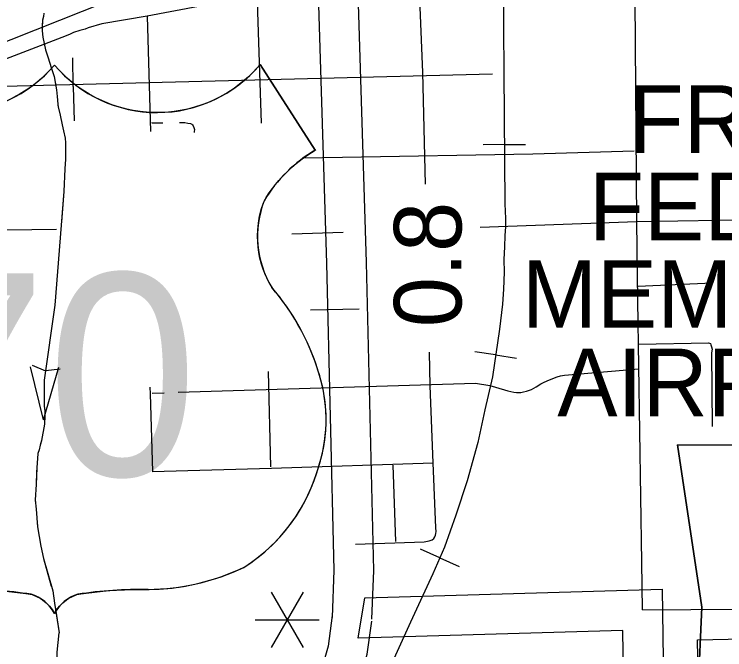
# Model space of a CAD drawing. Extents: x 1084508 to 1142749, y 1057638 to 1093403.
# Drawn here: x 1101630 to 1103026, y 1073047 to 1074295 of the extents above; entities that cross this region are included whole.
import ezdxf

# ---------------------------------------------------------------- set-up
doc = ezdxf.new("R2010")
doc.units = 0
for name, color, linetype in [('Level 10', 7, 'Continuous'), ('Level 15', 7, 'Continuous'), ('Level 21', 7, 'Continuous'), ('Level 22', 7, 'Continuous'), ('Level 33', 7, 'Continuous'), ('Level 34', 7, 'Continuous'), ('Level 35', 7, 'Continuous'), ('Level 40', 7, 'Continuous'), ('Level 43', 7, 'Continuous'), ('Level 48', 7, 'Continuous'), ('Level 57', 7, 'Continuous'), ('Level 6', 7, 'Continuous')]:
    doc.layers.add(name, color=color, linetype=linetype)

msp = doc.modelspace()

# ---------------------------------------------------------------- linework, layer by layer
at = {"layer": 'Level 10'}
msp.add_line((1102305.5, 1073070), (1102319.1, 1073148.9), dxfattribs=at)
for points in [[(1102319.1, 1073148.9), (1102903.4, 1073165.9), (1102916.4, 1072247.3), (1102924.5, 1071432.2), (1102929.4, 1071239.5), (1102926.3, 1071187.3), (1102905.3, 1071089.9)], [(1102848.9, 1071200.7), (1102848.3, 1071197.9), (1102850.9, 1071240.8), (1102846.1, 1071430.8), (1102838, 1072246.4), (1102826.1, 1073085.2), (1102305.5, 1073070)]]:
    msp.add_lwpolyline(points, dxfattribs=at)
at = {"layer": 'Level 15'}
for points in [[(1102224.1, 1074440.9), (1102243.7, 1073805.7), (1102258.1, 1073203.6), (1102254.5, 1073110.5)], [(1102332.9, 1073107.4), (1102336.7, 1073203), (1102322.2, 1073807.9), (1102302.5, 1074443.4)], [(1102254.8, 1073114.2), (1102246.6, 1073054.1), (1102235.2, 1073013), (1102230.6, 1072998.9), (1102210.8, 1072969.7), (1102197.7, 1072955.1), (1102173.8, 1072922.9), (1102155, 1072900), (1102143.6, 1072888.3), (1102116.9, 1072867), (1101851.5, 1072624), (1101364.1, 1072185.3), (1100217.6, 1071166.4), (1099385.1, 1070422.3)], [(1099437.4, 1070363.8), (1100269.9, 1071107.8), (1101416.4, 1072126.8), (1101904.3, 1072565.9), (1102168, 1072807.4), (1102196.3, 1072830.1), (1102213.4, 1072847.6), (1102235.6, 1072874.5), (1102258.6, 1072905.4), (1102272.7, 1072921.2), (1102301.9, 1072964.1), (1102310.4, 1072990.5), (1102323.6, 1073038.2), (1102332.6, 1073103.6)]]:
    msp.add_lwpolyline(points, dxfattribs=at)
at = {"layer": 'Level 21'}
for p, q in [((1102980.8, 1073131.1), (1102933.1, 1073449.7)), ((1102959.6, 1072647.8), (1102980.8, 1073131.1))]:
    msp.add_line(p, q, dxfattribs=at)
msp.add_lwpolyline([(1102933.1, 1073449.7), (1102980.8, 1073131.1), (1102959.6, 1072647.8), (1103002.1, 1072621.3), (1103081.7, 1072621.3), (1103081.7, 1072451.4), (1103750.8, 1072451.4), (1103782.7, 1072520.4), (1103772.1, 1072631.9), (1103788, 1072759.4), (1103846.4, 1072860.3), (1103883.6, 1072934.6), (1103936.7, 1073014.3), (1103968.6, 1073099.2), (1103995.1, 1073168.2), (1104042.9, 1073226.7), (1104053.5, 1073263.8), (1104032.3, 1073290.4), (1103867.7, 1073290.4), (1103904.8, 1073364.7), (1103910.1, 1073412.5), (1103888.1, 1073449.2)], close=True, dxfattribs=at)
msp.add_lwpolyline([(1102933.1, 1073449.7), (1103888.1, 1073449.2)], dxfattribs=at)
at = {"layer": 'Level 22'}
msp.add_line((1102113, 1074196.4), (1102221.6, 1074028.4), dxfattribs=at)
for points in [[(1101709.1, 1074195.5), (1101700.8, 1074186.2), (1101692.9, 1074178.1), (1101683.9, 1074169.7), (1101674.2, 1074161.4), (1101664.9, 1074154.2), (1101653.6, 1074146.2), (1101641.4, 1074138.6), (1101627.5, 1074131)], [(1102110.9, 1073230), (1102124, 1073241), (1102136.8, 1073252.8), (1102151.8, 1073268.4), (1102163.4, 1073281.9), (1102173.7, 1073295.1), (1102184.3, 1073310.3), (1102194.5, 1073326.8), (1102202.4, 1073341.1), (1102209.5, 1073355.8), (1102215.7, 1073370), (1102222.9, 1073389.4), (1102227.9, 1073405.4), (1102231.6, 1073418.2), (1102234.5, 1073429.5), (1102237.4, 1073442.5), (1102240.2, 1073459.5), (1102242, 1073477.6), (1102242.7, 1073492.9), (1102242.7, 1073508.6), (1102241.7, 1073525.3), (1102239.9, 1073540.6), (1102237.5, 1073555.3), (1102233.8, 1073571.8), (1102229.9, 1073586), (1102225.7, 1073599), (1102220.4, 1073614.7), (1102215.6, 1073627.5), (1102211.5, 1073637.4), (1102205.6, 1073650.9), (1102199.1, 1073664.5), (1102192.9, 1073676.3), (1102187.5, 1073686.2), (1102181.3, 1073696.7), (1102173.9, 1073708.4), (1102165.8, 1073720.4), (1102157.2, 1073732.4), (1102146.6, 1073746), (1102137.8, 1073756.5), (1102130.6, 1073768.2), (1102123.5, 1073783), (1102119, 1073794.4), (1102115.7, 1073804.7), (1102112.7, 1073816.3), (1102110.6, 1073827.1), (1102109.1, 1073838.5), (1102108.3, 1073847.9), (1102108, 1073859.5), (1102108.4, 1073872), (1102109.7, 1073884.8), (1102112.1, 1073898.7), (1102115.3, 1073911.7), (1102119.6, 1073924.8), (1102125.1, 1073935.4), (1102131.1, 1073944.5), (1102137.3, 1073953.2), (1102143.4, 1073961.1), (1102149.6, 1073968.5), (1102158.2, 1073978.1), (1102166.6, 1073986.6), (1102174.9, 1073994.4), (1102184.2, 1074002.4), (1102195.9, 1074011.5), (1102204.6, 1074017.7), (1102213.9, 1074023.7), (1102221.6, 1074028.4), (1102113, 1074196.4), (1102106.5, 1074189), (1102098.5, 1074180.5), (1102090.3, 1074172.6), (1102082.3, 1074165.5), (1102072.8, 1074157.8), (1102061.8, 1074149.7), (1102049.8, 1074141.8), (1102039, 1074135.5), (1102027.4, 1074129.4), (1102014.7, 1074123.5), (1102000.7, 1074118), (1101984.2, 1074112.6), (1101970.6, 1074109.1), (1101955.9, 1074106.1), (1101944.3, 1074104.4), (1101932.8, 1074103.1), (1101920.7, 1074102.4), (1101906.8, 1074102.2), (1101889.7, 1074103), (1101877.3, 1074104.3), (1101863.7, 1074106.4), (1101850.9, 1074109.1), (1101836.9, 1074112.7), (1101821.7, 1074117.6), (1101808.2, 1074122.9), (1101790.6, 1074131), (1101776.7, 1074138.6), (1101764.6, 1074146.2), (1101753.2, 1074154.2), (1101743.9, 1074161.4), (1101734.2, 1074169.7), (1101725.2, 1074178.1), (1101717.3, 1074186.2), (1101709.1, 1074195.5)], [(1101709.1, 1073118.3), (1101713.8, 1073126.1), (1101719.1, 1073132.9), (1101725.6, 1073139.5), (1101732.4, 1073144.9), (1101737.3, 1073148.2), (1101743, 1073151.3), (1101752.9, 1073155.4), (1101761.1, 1073157), (1101771, 1073158.4), (1101787.5, 1073160.5), (1101804.3, 1073162.2), (1101817.5, 1073163.3), (1101830.9, 1073164.2), (1101846.3, 1073165), (1101862.4, 1073165.5), (1101878.6, 1073165.7), (1101895.3, 1073165.6), (1101914.7, 1073166.3), (1101940.1, 1073168.4), (1101960.3, 1073171.2), (1101979, 1073174.7), (1101999, 1073179.3), (1102016.7, 1073184.2), (1102036.3, 1073190.6), (1102060.4, 1073199.8), (1102080.9, 1073209), (1102097.3, 1073219.7), (1102110.9, 1073230)], [(1101613.8, 1073162.2), (1101630.7, 1073160.5), (1101647.2, 1073158.4), (1101657.1, 1073157), (1101665.2, 1073155.4), (1101675.1, 1073151.3), (1101680.8, 1073148.2), (1101685.7, 1073144.9), (1101692.5, 1073139.5), (1101699, 1073132.9), (1101704.3, 1073126.1), (1101709.1, 1073118.3)]]:
    msp.add_lwpolyline(points, dxfattribs=at)
for centre, radius, start, end in [((1101507.5, 1074366.6), 264.4, 220.075, 319.6701), ((1101910.6, 1074366.6), 264.4, 220.3299, 319.925), ((1102363.6, 1073784.4), 282.3, 120.0117, 149.2191), ((1102301.5, 1073858.9), 193.5, 158.7892, 211.1895), ((1101795.5, 1073462.2), 451.5, 17.3087, 41.0435), ((1101944.5, 1073499.2), 298.3, 342.6181, 19.0424), ((1101895.9, 1073500.1), 345.2, 302.8688, 344.8926), ((1101889.5, 1073608.8), 443.2, 270.4221, 295.9229), ((1101538.9, 1072353.8), 811.9, 81.1942, 90.9539), ((1101879.3, 1072353.8), 811.9, 89.0461, 98.8058), ((1101640.4, 1073081.7), 77.8, 28.0342, 72.9864), ((1101777.7, 1073081.7), 77.8, 107.0136, 151.9658)]:
    msp.add_arc(centre, radius, start, end, dxfattribs=at)
at = {"layer": 'Level 33'}
for points in [[(1103154, 1074659), (1103175.5, 1073892.7), (1102853.2, 1073887.4), (1102545.7, 1073876.2)], [(1102863.3, 1073218.9), (1102855.6, 1073732.4), (1102853.2, 1073887.4), (1102849, 1074500.2)], [(1102105.3, 1074387.8), (1102107.1, 1074319.9), (1102115, 1074081.1)], [(1102227.8, 1074319.9), (1102106.5, 1074319), (1102070, 1074318.3), (1102057.4, 1074318.4), (1102049.3, 1074318), (1102035.5, 1074316.1), (1102024.2, 1074314.7), (1102010.2, 1074312.5), (1101999.9, 1074311.1), (1101992.3, 1074310.7), (1101890.9, 1074291.4), (1101802, 1074276.1), (1101774.9, 1074268.6), (1101769.1, 1074266.1), (1101758.8, 1074263.1), (1101746.7, 1074259.1), (1101739.6, 1074256.3), (1101731.9, 1074252.5), (1101259.9, 1074071.7), (1101243, 1074064), (1101239.3, 1074062.3), (1101235.3, 1074059), (1101228.7, 1074052.4), (1101201.5, 1074010.2)], [(1101712.7, 1073872.6), (1101566.4, 1073870.8), (1101545.6, 1073870.6), (1101542.4, 1073871.8), (1101540.3, 1073873.1), (1101539.4, 1073873.9), (1101538.5, 1073875), (1101537.7, 1073877.5), (1101537.2, 1073883.1), (1101537.9, 1074178.2)], [(1101745.8, 1074153.6), (1101747.6, 1074085.7)], [(1101900.1, 1074082.3), (1101900.1, 1074082), (1101922.1, 1074082.2)], [(1101954.4, 1074082.3), (1101964.9, 1074082.4), (1101971.3, 1074081.1), (1101976.3, 1074080.4), (1101978.9, 1074079.6), (1101980.2, 1074078), (1101981.6, 1074076.2), (1101983, 1074073.1), (1101984.1, 1074069.1), (1101983.6, 1074065), (1101983.7, 1074062.7)], [(1102195.9, 1074013), (1102274.8, 1074014.7), (1102648.9, 1074021.3), (1102847.9, 1074026.7)], [(1102276, 1073866.4), (1102175.1, 1073863.2)], [(1102856.1, 1073761.2), (1103001.5, 1073767.7)], [(1102856.1, 1073761.2), (1103001.5, 1073767.7)], [(1102212.1, 1073714.5), (1102307.9, 1073717)], [(1102857.5, 1073647.6), (1102994.2, 1073650.2), (1102997.8, 1073648.5), (1102998.9, 1073645.7), (1103000, 1073642), (1103001.1, 1073637.6), (1103000.2, 1073630), (1103001.7, 1073485.8)], [(1102129, 1073593.3), (1102133.7, 1073406.1)], [(1101952.1, 1073552.9), (1102536.2, 1073570.9), (1102544.2, 1073569.3), (1102556.9, 1073567.4), (1102560.7, 1073566.6), (1102564.8, 1073565.8)], [(1101900.9, 1073551.3), (1101924.5, 1073552)], [(1102373.9, 1073409.9), (1102378.9, 1073259.6)], [(1102864.8, 1073125.5), (1102863.3, 1073218.9)], [(1102864.8, 1073125.5), (1103626.6, 1073131.1), (1103642.3, 1073132.6), (1103659.5, 1073134.4), (1103676.4, 1073135.3), (1103690.7, 1073139.2), (1103700.8, 1073136.7), (1103722.3, 1073131.2), (1103731.3, 1073125.2), (1103767.3, 1073108.2), (1103779.8, 1073102.1), (1103791.3, 1073096.5), (1103803.3, 1073093.5), (1103818.4, 1073091.8), (1103835, 1073091.4), (1103972.9, 1073095.8), (1103984.1, 1073099.3), (1103986.8, 1073102.2), (1103990.4, 1073107.1), (1103993.1, 1073113.1), (1103993.8, 1073118.8), (1103994.5, 1073125.7), (1103991.2, 1073168.3)]]:
    msp.add_lwpolyline(points, dxfattribs=at)
at = {"layer": 'Level 34'}
for points in [[(1102438.2, 1073961.5), (1102432.7, 1074181.1), (1102420.2, 1074486.4), (1102416.1, 1074651.6)], [(1101948.4, 1074472.9), (1101951.1, 1074376), (1101530, 1074208.3), (1101200.6, 1074077.7)], [(1101890.9, 1074291.4), (1101897.7, 1074065.2)], [(1101745.8, 1074153.6), (1101744.9, 1074209.6)], [(1101609.3, 1074153.9), (1102569.7, 1074178.4)], [(1102300.4, 1073254.8), (1102435.5, 1073259.3), (1102445.2, 1073261), (1102449.2, 1073262.1), (1102451.1, 1073262.8), (1102454.4, 1073265.5), (1102456.5, 1073268.7), (1102457.6, 1073271.9), (1102458.1, 1073275.4), (1102458.8, 1073279.2), (1102458.2, 1073286.4), (1102453, 1073414.1), (1102447.4, 1073565.6), (1102445.9, 1073631.3)], [(1102564.8, 1073565.8), (1102593.2, 1073557.7), (1102599.9, 1073555.8), (1102611.9, 1073552.8), (1102617, 1073552.7), (1102625.5, 1073552.5), (1102630.8, 1073553.7), (1102636.7, 1073554.9), (1102646.6, 1073558.5), (1102655.5, 1073563.3), (1102665, 1073569.1), (1102671.5, 1073572.8), (1102681.9, 1073577.4), (1102686.9, 1073579.2), (1102691.5, 1073581.3), (1102696.5, 1073583.1), (1102703.6, 1073585), (1102711.1, 1073586.2), (1102857.6, 1073599.1)], [(1101896.7, 1073562.6), (1101896.9, 1073549.9), (1101901.9, 1073397)], [(1101900.7, 1073397), (1102135.7, 1073403.7), (1102453, 1073414.1)]]:
    msp.add_lwpolyline(points, dxfattribs=at)
at = {"layer": 'Level 35'}
msp.add_lwpolyline([(1102045.1, 1072127.2), (1102063.2, 1072196.2), (1102066.6, 1072224.3), (1102064.5, 1072239.3), (1102062.1, 1072247.4), (1102043.6, 1072265), (1102024.7, 1072275.6), (1102015, 1072285.6), (1101993.9, 1072316), (1101976.1, 1072331.1), (1101946, 1072351.4), (1101786.9, 1072447.1), (1101749.9, 1072482.6), (1101742.9, 1072494.6), (1101740.9, 1072507.4), (1101741, 1072562), (1101754.9, 1072792.3), (1101753.9, 1072814.3), (1101736, 1072909.1), (1101725, 1072946.4), (1101715.8, 1072985.6), (1101714.3, 1073004.7), (1101714.6, 1073042.1), (1101718, 1073080.5)], dxfattribs=at)
at = {"layer": 'Level 40'}
for p, q in [((1102593, 1074039.3), (1102551.6, 1074039)), ((1102593, 1074039.3), (1102634.4, 1074039.6)), ((1102575.9, 1073626.1), (1102534.9, 1073632.1)), ((1102575.9, 1073626.1), (1102616.9, 1073620.1)), ((1102466.2, 1073227.6), (1102428.3, 1073244.5)), ((1102466.2, 1073227.6), (1102504, 1073210.7))]:
    msp.add_line(p, q, dxfattribs=at)
for points in [[(1102491.7, 1077837.5), (1102504.8, 1077152.1), (1102528.5, 1076343.6), (1102542.3, 1075805), (1102563.2, 1075169.4), (1102589.2, 1074527.3), (1102593.9, 1073922.8), (1102595.2, 1073894.2), (1102595, 1073877.8), (1102594.2, 1073860.7), (1102593, 1073838.3), (1102592.3, 1073813.4), (1102592.5, 1073788.5), (1102591.1, 1073755.1), (1102589.6, 1073725.7), (1102583.4, 1073676.9), (1102569.7, 1073583.4), (1102555, 1073518.5), (1102540.6, 1073454.2), (1102519.8, 1073378.6), (1102498, 1073311.2), (1102475.6, 1073248.8), (1102452.2, 1073196.4), (1102408.8, 1073101.5)], [(1102510.8, 1076946.7), (1102528.5, 1076343.6), (1102542.3, 1075805), (1102563.2, 1075169.4), (1102589.2, 1074527.3), (1102593.9, 1073922.8), (1102595.2, 1073894.2), (1102595, 1073877.8), (1102594.2, 1073860.7), (1102593, 1073838.3), (1102592.3, 1073813.4), (1102592.5, 1073788.5), (1102591.1, 1073755.1), (1102589.6, 1073725.7), (1102583.4, 1073676.9), (1102569.7, 1073583.4), (1102555, 1073518.5), (1102540.6, 1073454.2), (1102519.8, 1073378.6), (1102498, 1073311.2), (1102475.6, 1073248.8), (1102452.2, 1073196.4), (1102408.8, 1073101.5), (1102181.1, 1072600.9)], [(1102408.8, 1073101.5), (1102181.1, 1072600.9), (1101788.4, 1071734.1), (1101483.2, 1071066.9), (1101096.9, 1070214.2), (1100585.6, 1069095.1), (1100076.5, 1067974.2), (1099522.2, 1066771.7), (1099036.2, 1065677.8)]]:
    msp.add_lwpolyline(points, dxfattribs=at)
at = {"layer": 'Level 43'}
for p, q in [((1101687.6, 1073498.5), (1101661.9, 1073603.1)), ((1101664.9, 1073606.2), (1101691.3, 1073594.9)), ((1101687.6, 1073498.5), (1101717.7, 1073601.9)), ((1101720.1, 1073598.4), (1101691.7, 1073594.9))]:
    msp.add_line(p, q, dxfattribs=at)
for points in [[(1101688.3, 1074297.5), (1101687.4, 1074291.1), (1101685.8, 1074283.8), (1101685, 1074273.4), (1101684.9, 1074262.7), (1101686.1, 1074250.4), (1101691.6, 1074225.2), (1101696.7, 1074209.6), (1101702.6, 1074190.4), (1101705.2, 1074182.9), (1101708.5, 1074172.7), (1101710.2, 1074161.7), (1101712.8, 1074146.7), (1101714, 1074133.9), (1101715.3, 1074118.8), (1101716.5, 1074113.2), (1101720.4, 1074096.7), (1101724.4, 1074078), (1101726.8, 1074066.1), (1101729.7, 1074051.7), (1101730.7, 1074042.6), (1101730.8, 1074026.3), (1101730.6, 1074010.5), (1101729.6, 1073991.9), (1101727.5, 1073947.1), (1101709.6, 1073724.2), (1101688.9, 1073576.8), (1101689, 1073562), (1101688.6, 1073543.1), (1101689, 1073525.8), (1101690.1, 1073516.4), (1101690.2, 1073506.6), (1101689.1, 1073490.5), (1101683.3, 1073458.1), (1101680.9, 1073449.2), (1101678.8, 1073439.7), (1101676.6, 1073432.3), (1101674.1, 1073404.5), (1101673, 1073371.7), (1101671.3, 1073341.7), (1101673, 1073323.2), (1101675.9, 1073288.7), (1101682, 1073250.8), (1101687.5, 1073226.5), (1101705.5, 1073162.7), (1101709.1, 1073138.6), (1101718, 1073080.5)], [(1101685.4, 1074278.1), (1101685, 1074273.4), (1101684.9, 1074262.7), (1101686.1, 1074250.4), (1101691.6, 1074225.2), (1101696.7, 1074209.6), (1101702.6, 1074190.4), (1101705.2, 1074182.9), (1101708.5, 1074172.7), (1101710.2, 1074161.7), (1101711, 1074157.3)], [(1101715.9, 1074116.2), (1101716.5, 1074113.2), (1101720.4, 1074096.7), (1101723.6, 1074081.6)], [(1101727.7, 1073952.1), (1101727.5, 1073947.1), (1101722.8, 1073887.8)], [(1101695.3, 1073622.3), (1101688.9, 1073576.8), (1101689, 1073562), (1101688.6, 1073543.1), (1101689, 1073525.8), (1101690.1, 1073516.4), (1101690.2, 1073506.6), (1101689.6, 1073498.6)], [(1101683.2, 1073457.7), (1101680.9, 1073449.2), (1101678.8, 1073439.7), (1101676.6, 1073432.3), (1101674.1, 1073404.5), (1101673.8, 1073396.5)], [(1101673.8, 1073396.5), (1101673, 1073371.7), (1101671.3, 1073341.7), (1101672, 1073334.4)], [(1101675.5, 1073293.2), (1101675.9, 1073288.7), (1101682, 1073250.8), (1101687.5, 1073226.5), (1101702.8, 1073172.1)], [(1101710.2, 1073131.4), (1101718, 1073080.5)]]:
    msp.add_lwpolyline(points, dxfattribs=at)
at = {"layer": 'Level 48'}
for p, q in [((1102197.6, 1073160.4), (1102134.9, 1073051.7)), ((1102134.9, 1073160.4), (1102197.6, 1073051.7)), ((1102103.5, 1073106.1), (1102229, 1073106.1))]:
    msp.add_line(p, q, dxfattribs=at)
at = {"layer": 'Level 6'}
msp.add_lwpolyline([(1103273.6, 1072241.8), (1102988, 1072235.9), (1102972.5, 1073066.7), (1104534.3, 1073100.5)], dxfattribs=at)

# ---------------------------------------------------------------- texts
at = {"layer": 'Level 22'}
msp.add_text('70', height=397.75, dxfattribs=at).set_placement((1101398.7, 1073388.7))
at = {"layer": 'Level 48'}
msp.add_text('0.8', height=132.58, rotation=90, dxfattribs=at).set_placement((1102508.7, 1073680.5))
at = {"layer": 'Level 57'}
for s, p in [('FRANK', (1102836.8, 1074023)), ('FEDERER', (1102759.1, 1073851.3)), ('MEMORIAL', (1102627.4, 1073679.5)), ('AIRPORT', (1102697.1, 1073505.8))]:
    msp.add_text(s, height=132.58, dxfattribs=at).set_placement(p)

doc.saveas('drawing.dxf')
